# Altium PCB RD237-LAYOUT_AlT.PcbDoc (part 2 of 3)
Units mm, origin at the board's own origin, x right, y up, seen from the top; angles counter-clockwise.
Board outline 100 x 82 mm, 4 copper layers (Top Layer, GND2, POWER 3, Bottom Layer), stack 1.444 mm thick; 308 components, 134 nets, 738 pads, 304 vias.
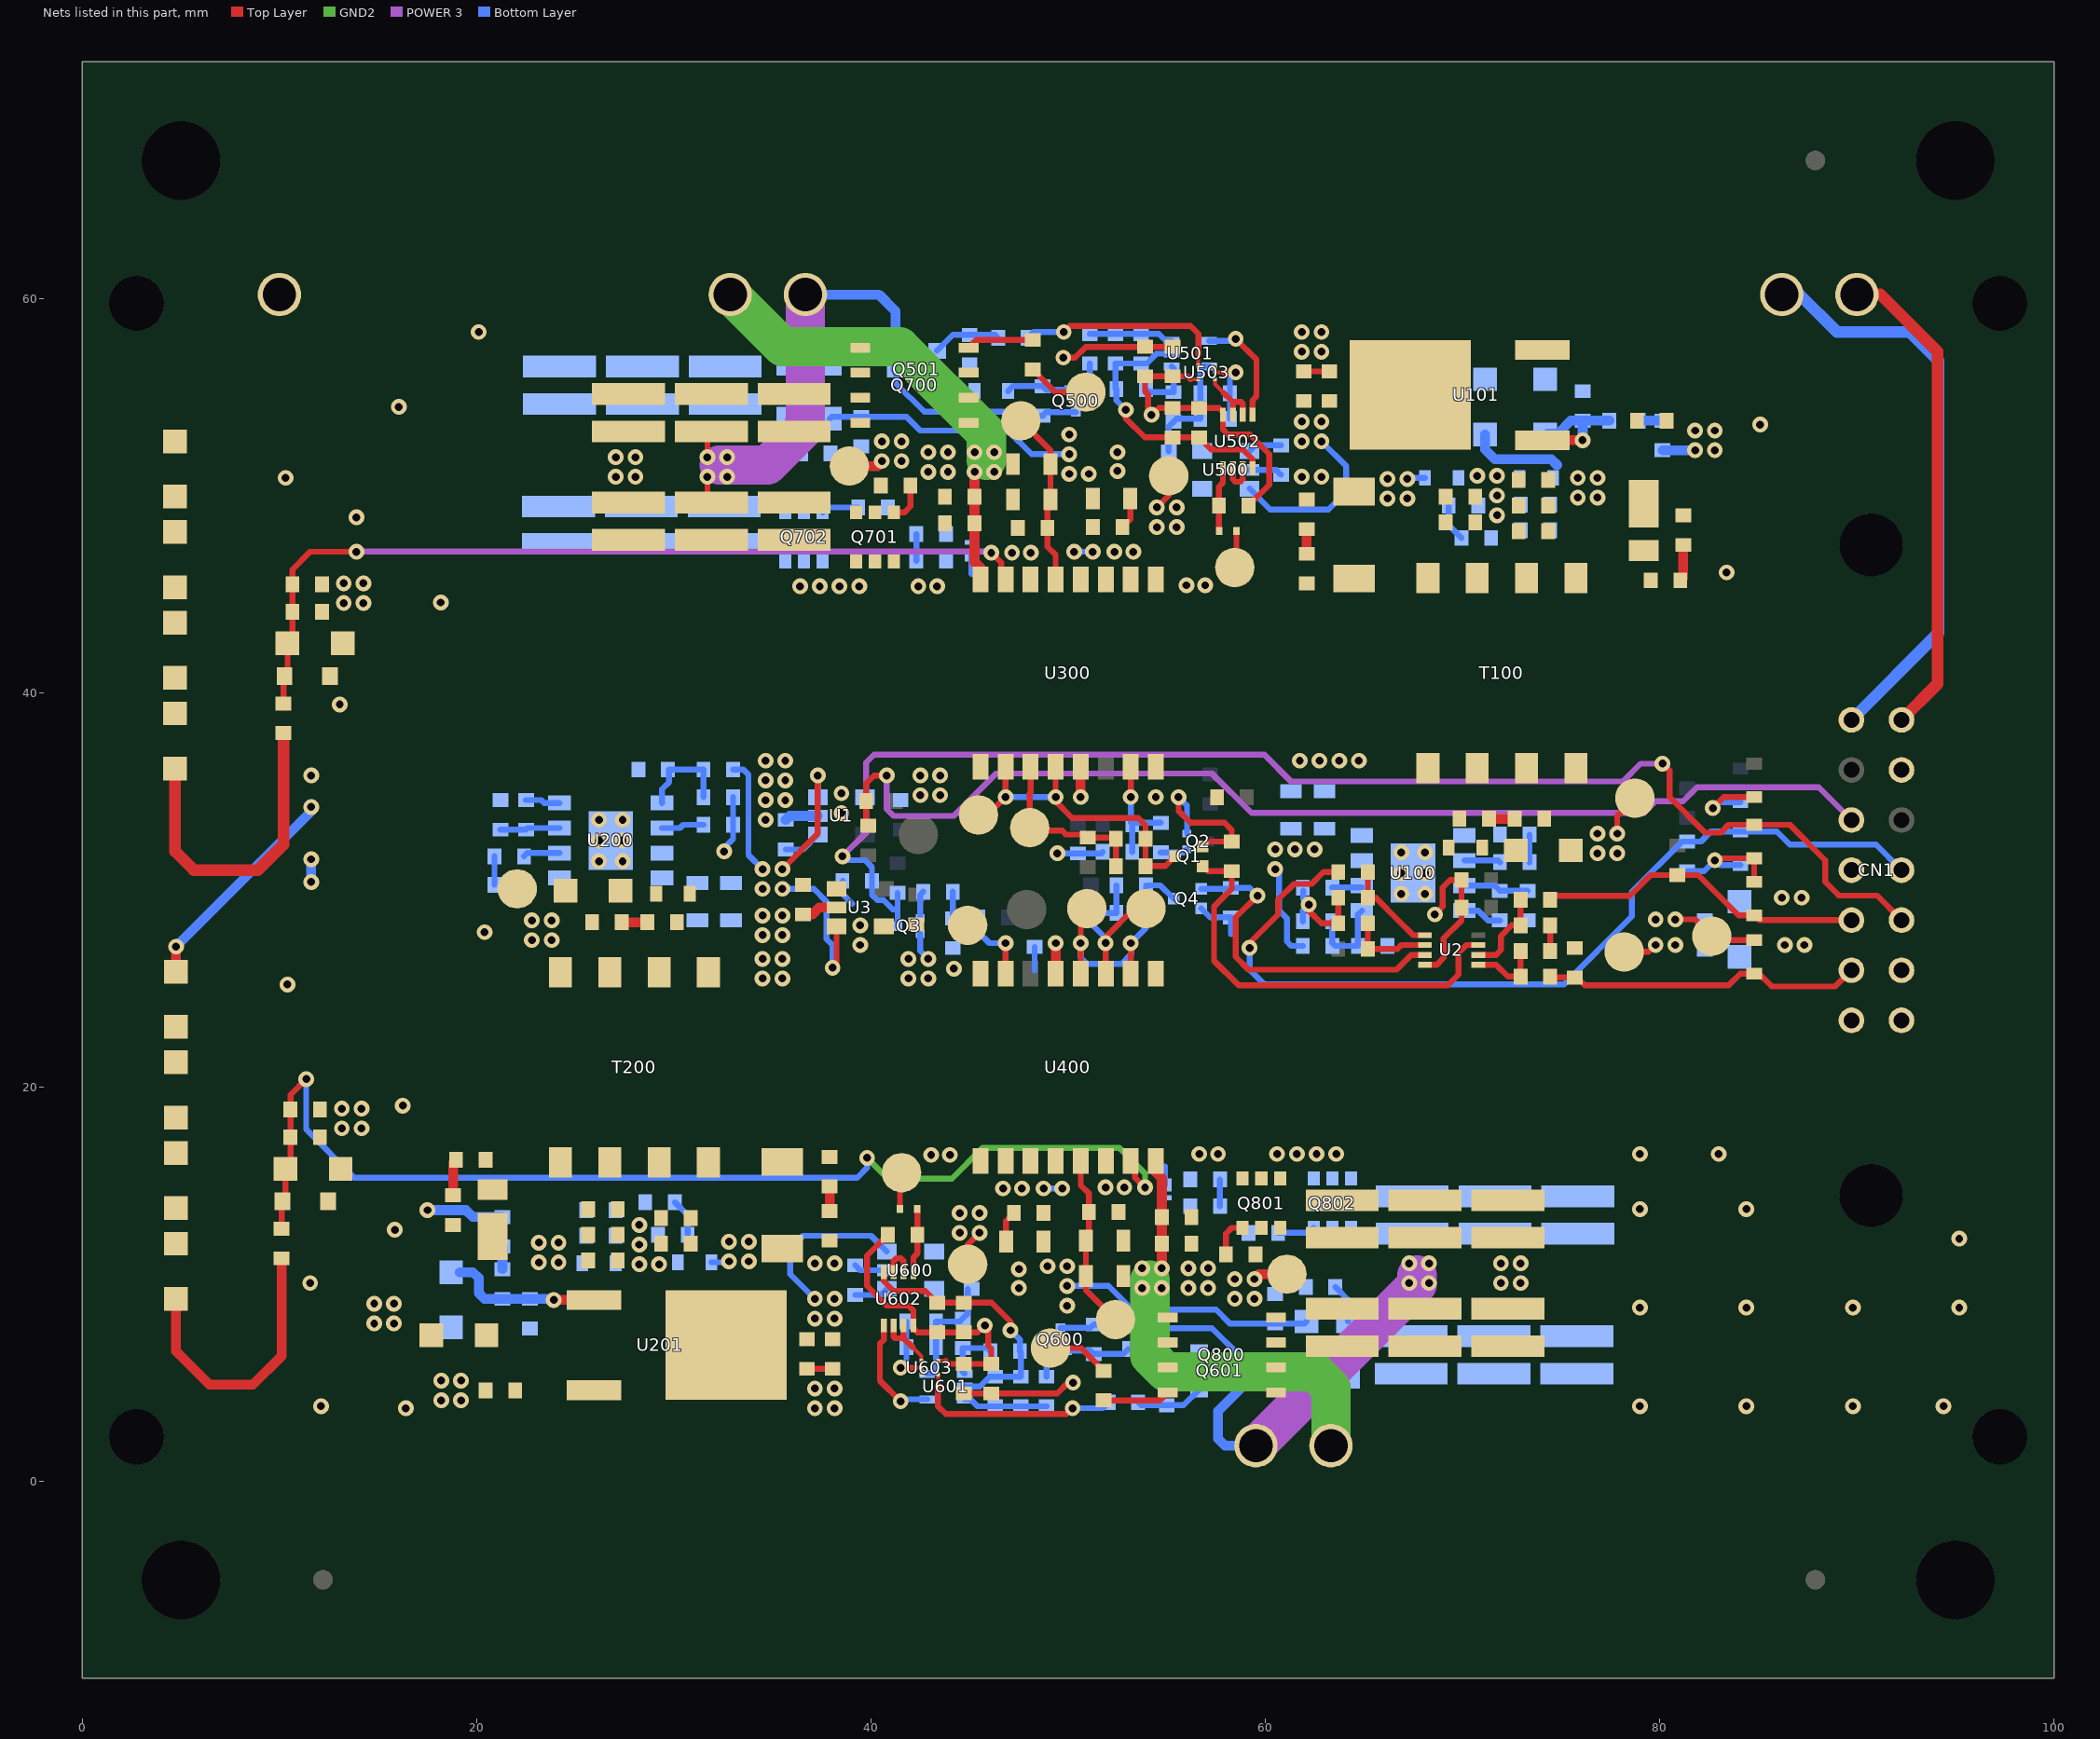
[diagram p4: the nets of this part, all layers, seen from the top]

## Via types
v1: diameter 0.8, hole 0.4, Top Layer to Bottom Layer, 304 vias

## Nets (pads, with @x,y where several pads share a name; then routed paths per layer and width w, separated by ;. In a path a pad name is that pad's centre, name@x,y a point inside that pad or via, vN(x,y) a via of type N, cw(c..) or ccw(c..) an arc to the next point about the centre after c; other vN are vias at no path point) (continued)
A_INA: CN1.7 D2.1 R9.2 R13.2 | length 45.9
  Top Layer w0.3: v1(59.2,27.05) 59.2,27.3 60.65,28.75 60.65,29.5 61.45,30.3 62.35,30.3 62.95,30.9 R9.2@63.7,30.9
  Bottom Layer w0.3: v1(59.2,27.05) 59.2,25.95 59.95,25.2 75.15,25.2 78.6,28.65 78.6,29.9 81.15,32.45 R13.2@81.4,32.45 82.1,32.45 82.6,32.95 D2.1@84.1,32.95 85.95,32.95 86.61,32.29 90.98,32.29 CN1.7@92.27,31
A_INB(NC): CN1.10 R20.2 R21.2 | length 57.1
  Top Layer w0.3: R21.2@39.85,33.25 39.75,33.35 R20.2@39.75,34.5 39.75,35.4 40.15,35.8 v1(40.8,35.8)
  POWER 3 w0.3: v1(40.8,35.8) 40.8,34.1 41.15,33.75 44.2,33.75 46.35,35.9 57.3,35.9 59.3,33.9 79.2,33.9 79.8,34.5 81.2,34.5 81.9,35.2 88.07,35.2 CN1.10@89.73,33.54
B_ENA: CN1.6 D3.1 R4.2 R6.2 | length 16.7
  Top Layer w0.3: R6.2@74.45,29.5 74.65,29.7 78.5,29.7 79.55,30.75 R4.2@80.9,30.75 81.95,30.75 84,28.7 D3.1@84.8,28.7 85.04,28.46 CN1.6@89.73,28.46
B_FLT: C19.2 CN1.5 D6.1 Q3.3 R16.1 | length 70.3
  Top Layer w0.3: v1(80.15,36.4) 80.5,36.05 80.5,34.7 82.3,32.9 83.1,32.9 83.5,33.3 D6.1@84.8,33.3 86.6,33.3 88.4,31.5 88.4,30.4 89.09,29.71 91.02,29.71 CN1.5@92.27,28.46
  POWER 3 w0.3: v1(38.55,31.7) 39.75,32.9 39.75,36.45 40.15,36.85 59.95,36.85 61.3,35.5 78.15,35.5 79.05,36.4 v1(80.15,36.4)
  Bottom Layer w0.3: v1(38.55,31.7) 38.75,31.5 39.7,31.5 40.05,31.15 C19.2@40.05,30.45 40.05,29.75 40.325,29.475 40.625,29.475 41.093,29.006 41.344,29.006 ; Q3.3@41.35,28.15 41.35,29 R16.1@41.35,29.85
B_INA: CN1.4 D5.1 R7.2 R14.2 | length 16.3
  Top Layer w0.3: R7.2@74.45,25.6 74.5,25.55 R14.2@75.7,25.55 75.8,25.55 76.2,25.15 83.5,25.15 84.1,25.75 D5.1@84.8,25.75 85.032,25.75 85.682,25.1 88.91,25.1 CN1.4@89.73,25.92
B_INB(NC): CN1.3
B_RDY(NC): CN1.8
GND: C1.1 C2.1 C3.1 C4.1 C6.1 C7.1 C8.1 C9.1 C10.1 C11.1 C12.1 C13.1 C15.1 C16.1 C17.1 C18.1 C19.1 C100.1 C101.1 C102.1 C114.1 C200.1 C201.1 C202.1 C214.1 CN1.1 CN1.11 D1.1 D2.2 D3.2 D4.2 D5.2 D6.2 D7.2 Q1.2 Q2.2 Q3.2 Q4.2 R11.1 R13.1 R14.1 R22.1 R101.1 R106.1 R201.1 R206.1 TP3.1 TP17.1 U1.2 U2.4 U3.2 U100.4 U100.9 U200.4 U200.9 U300.5 U300.8 U400.5 U400.8 | length 55.5
  Top Layer w0.3: v1(55.6,34.7) 55.6,34 56.2,33.4 57.925,33.4 58.3,33.025 R11.1@58.3,32.45 57.075,32.45 Q1.2@56.825,32.2 ; v1(62.2,29.25) 62.2,28.95 62.85,28.3 C9.1@63.7,28.3 C10.1@63.7,29.6 ; U2.4@68.1,26.2 68.7,26.2 69.05,26.55 69.05,27.55 69.95,28.45 C8.1@69.95,29.1 C7.1@69.95,30.5 69.375,30.5 69,30.125 69,29.15 v1(68.6,28.75) ; C11.1@74.45,26.9 C12.1@74.45,28.2 ; v1(80.8,28.5) 81.8,28.5 TP3.1@82.65,27.65 82.85,27.45 D5.2@84.8,27.45 ; v1(82.7,34.15) 83.25,34.7 D7.2@84.8,34.7 ; v1(82.8,31.5) 82.9,31.6 D6.2@84.8,31.6 D3.2@84.8,30.4
  Top Layer w0.5: C16.1@36.55,28.75 37.021,28.75 37.371,29.1 U3.2@38.25,29.1 ; U400.5@49.365,25.75 v1(49.365,27.295) ; v1(50.635,34.705) U300.5@50.635,36.25
  Bottom Layer w0.3: v1(32.55,31.95) 32.55,32.127 33,32.577 C200.1@33,33.3 C214.1@33,34.7 ; C19.1@38.575,30.45 38.575,29.775 39.05,29.3 ; Q3.2@42.5,27.75 42.5,26.9 v1(42.9,26.5) ; 48.3,25.9 C13.1@48.3,27.1 ; v1(49.45,31.85) C4.1@50.5,31.85 51.675,31.85 C6.1@51.75,31.925 ; v1(55.6,34.7) 56.025,34.275 Q2.2@56.025,32.85 ; Q4.2@56.75,29.05 57.2,28.6 R22.1@58.25,28.6 58.25,27.75 ; C114.1@61.9,28.4 61.9,28.95 v1(62.2,29.25) 61.934,29.516 C100.1@61.934,29.961 ; R13.1@81.4,30.95 82.25,30.95 v1(82.8,31.5) 83.05,31.25 D2.2@84.1,31.25 ; v1(82.7,34.15) 83,34.45 D4.2@84.1,34.45
  Bottom Layer w0.5: C2.1@35.675,33.55 35.875,33.75 U1.2@37.3,33.75
  other v1: 34.5,25.5 35.5,25.5 41.9,25.5 42.9,25.5 44.2,26 34.5,26.5 35.5,26.5 41.9,26.5 39.45,27.2 34.5,27.7 35.5,27.7 20.4,27.85 39.45,28.2 79.8,28.5 34.5,28.7 35.5,28.7 86.2,29.6 87.2,29.6 66.9,29.8 68.1,29.8 66.9,30.85 68.1,30.85 26.2,31.45 27.4,31.45 66.9,31.9 68.1,31.9 26.2,32.5 27.4,32.5 26.2,33.55 27.4,33.55 34.65,33.55 38.5,33.895 34.65,34.55 35.65,34.55 54.445,34.705 42.5,34.8 43.5,34.8 38.5,34.895 34.65,35.55 35.65,35.55 42.5,35.8 43.5,35.8 34.65,36.55 35.65,36.55 61.75,36.55 62.75,36.55 63.75,36.55 64.75,36.55
NC_1A: U500.4
NC_1B: U600.4
NC_2A: U503.3
NC_2B: U603.3
NC_A: U1.4
NC_B: U3.4
NetC5_1: C5.1 Q1.3 R5.1 TP7.1 U300.2 U300.4 | length 16.4
  Top Layer w0.3: TP7.1@45.45,33.8 45.92,33.8 v1(46.825,34.705) U300.2@46.825,36.25 ; U300.4@49.365,36.25 v1(49.365,34.705) 49.365,34.485 50.2,33.65 53.55,33.65 53.925,33.275 C5.1@53.925,32.6 R5.1@53.925,31.2 54.925,31.2 Q1.3@55.425,31.7
  Bottom Layer w0.3: v1(46.825,34.705) v1(49.365,34.705)
NetC5_2: C5.2 R1.1 R5.2 TP8.1 U300.3 | length 9.1
  Top Layer w0.3: U300.3@48.095,36.25 48.095,34.95 48.05,34.905 TP8.1@48.05,33.15 48.2,33 49.7,33 49.9,32.8 50.85,32.8 R1.1@51,32.65 52.375,32.65 C5.2@52.425,32.6 R5.2@52.425,31.2
NetC6_2: C6.2 R3.1 R8.2 U300.7 | length 5.8
  Top Layer w0.3: v1(53.175,34.705) U300.7@53.175,36.25
  Bottom Layer w0.3: v1(53.175,34.705) 53.175,33.4 R3.1@53.25,33.325 ; C6.2@53.25,31.925 R3.1@53.25,33.325 ; R8.2@54.7,33.4 53.325,33.4 R3.1@53.25,33.325
NetC9_2: C9.2 R10.1 U2.2 | length 4.2
  Top Layer w0.3: C9.2@65.2,28.3 R10.1@65.2,27 66.65,27 ; 66.7,27 66.9,27.2 U2.2@68.1,27.2
NetC10_2: C10.2 R9.1 U2.1 | length 5
  Top Layer w0.3: R9.1@65.2,30.9 C10.2@65.2,29.6 65.6,29.6 66.75,28.45 67.5,27.7 U2.1@68.1,27.7
NetC11_2: C11.2 R7.1 U2.5 | length 3.7
  Top Layer w0.3: U2.5@70.8,26.2 71.7,26.2 72.3,25.6 R7.1@72.95,25.6 C11.2@72.95,26.9
NetC12_2: C12.2 R6.1 U2.6 | length 4.7
  Top Layer w0.3: U2.6@70.8,26.7 71.7,26.7 71.95,26.95 71.95,27.65 72.5,28.2 C12.2@72.95,28.2 R6.1@72.95,29.7
NetC14_1: C14.1 Q4.3 R18.1 TP19.1 U400.2 U400.4 | length 14.1
  Top Layer w0.3: U400.4@50.635,25.75 v1(50.635,27.295) 50.635,28.735 TP19.1@50.95,29.05 ; U400.2@53.175,25.75 v1(53.175,27.295)
  Bottom Layer w0.3: v1(50.635,27.295) 50.635,26.565 50.95,26.25 52.7,26.25 53.175,26.725 v1(53.175,27.295) 53.95,28.07 R18.1@53.95,28.825 C14.1@53.95,30.225 54.675,30.225 Q4.3@55.35,29.55
NetC14_2: C14.2 R15.1 R18.2 TP18.1 U400.3 | length 9
  Top Layer w0.3: U400.3@51.9,25.755 v1(51.9,27.3) 51.9,27.6 53.35,29.05 TP18.1@53.95,29.05
  Bottom Layer w0.3: v1(51.9,27.3) 51.9,27.55 51.15,28.3 R15.1@51.15,28.775 51.2,28.825 R18.2@52.45,28.825 C14.2@52.45,30.225
NetC15_2: C15.2 R17.1 R19.2 U400.7 | length 6.6
  Top Layer w0.3: U400.7@46.825,25.75 v1(46.825,27.295)
  Bottom Layer w0.3: R19.2@44.15,29.9 C15.2@44.15,28.55 44.2,28.6 R17.1@45.45,28.6 45.45,27.85 46.005,27.295 v1(46.825,27.295)
NetC100_2: C100.2 U100.2 | length 1.5
  Bottom Layer w0.3: C100.2@63.4,30.115 U100.2@64.898,30.115
NetC103_1: C103.1 D101.1 R105.1 T100.1 T100.2 TP100.1 U100.5 | length 2.2
  Top Layer w0.3: v1(77.85,32.85) 77.85,33.75 TP100.1@78.75,34.65
  other v1: 76.85,31.85 77.85,31.85 76.85,32.85
NetC103_2: C103.2 R102.1 | length 1.3
  Top Layer w0.5: R102.1@71.35,33.6 C103.2@72.65,33.6
NetC104_1: C104.1 C106.2 C108.2 C110.2 C111.2 D102.1 D104.1 D106.2 R110.2 R112.2 U101.3 | length 4.7
  Bottom Layer w0.5: D106.2@71.15,53.1 71.15,52.345 71.645,51.85 74.5,51.85 74.8,51.55
  other v1: 75.85,49.9 76.85,49.9 75.85,50.9 76.85,50.9
NetC104_2: C104.2 R107.1 | length 1.9
  Top Layer w0.5: R107.1@81.05,45.7 81.2,45.85 C104.2@81.2,47.5
NetC105_2: C105.2 R108.1 | length 1.3
  Top Layer w0.5: R108.1@62.1,47.05 C105.2@62.1,48.3
NetC114_2: C114.2 R100.1 R101.2 U100.1 | length 4.3
  Bottom Layer w0.3: C114.2@63.4,28.4 63.4,27.3 63.55,27.15 R101.2@64.7,27.15 64.7,28.747 U100.1@64.898,28.945
NetC200_2: C200.2 U200.2 | length 2.2
  Bottom Layer w0.3: U200.2@29.401,33.135 30.31,33.135 30.475,33.3 C200.2@31.5,33.3
NetC203_1: C203.1 D201.1 R205.1 T200.1 T200.2 TP200.1 U200.5
  other v1: 22.8,27.45 23.8,27.45 22.8,28.45 23.8,28.45
NetC203_2: C203.2 R202.1 | length 1.3
  Top Layer w0.5: C203.2@27.35,28.35 R202.1@28.65,28.35
NetC204_1: C204.1 C206.2 C208.2 C210.2 C211.2 D202.1 D204.1 D206.2 R210.2 R212.2 U201.3
  other v1: 23.15,11.1 24.15,11.1 23.15,12.1 24.15,12.1
NetC204_2: C204.2 R207.1 | length 1.9
  Top Layer w0.5: C204.2@18.8,14.5 18.8,16.15 R207.1@18.95,16.3
NetC205_2: C205.2 R208.1 | length 1.3
  Top Layer w0.5: C205.2@37.9,13.7 R208.1@37.9,14.95
NetC214_2: C214.2 R200.1 R201.2 U200.1 | length 5
  Bottom Layer w0.3: U200.1@29.401,34.405 29.401,35.101 29.75,35.45 29.75,36.1 R200.1@31.5,36.1 C214.2@31.5,34.7
NetC501_2: C501.2 C503.2 C504.2 C505.2 C506.2 C507.2 C508.2 R500.2 R505.2 U500.5 U501.5 U502.8 U503.5 | length 21.5
  Top Layer w0.2: 56.2,55.9 U503.5@56.6,55.9
  Top Layer w0.3: v1(54.225,54.1) 54.05,54.275 54.05,55.138 53.9,55.288 C507.2@53.9,56.05 C508.2@55.3,56.05 56.05,56.05 56.2,55.9 ; v1@54.25,54.1 54.6,54.45 C505.2@55.3,54.45 C506.2@56.65,54.45 57.65,54.45 57.85,54.25 U502.8@57.85,54.1 57.85,53.35 58.1,53.1 59.2,53.1 60.2,52.1 60.2,50.55 R505.2@59.15,49.5
  Bottom Layer w0.3: C501.2@55.1,52.25 55.1,53.5 R500.2@55.35,53.75 55.5,53.9 C503.2@56.7,53.9 C504.2@56.7,55.2 56.7,56.4 56.85,56.55 U501.5@57.15,56.55
NetC502_2: C502.2 R503.1 R504.2 U501.3 | length 4.3
  Bottom Layer w0.3: R503.1@51.1,58.2 C502.2@52.4,58.2 R504.2@53.7,58.2 54.6,58.2 54.95,57.85 U501.3@55.25,57.85
NetC601_2: C601.2 C603.2 C604.2 C605.2 C606.2 C607.2 C608.2 R600.2 R605.2 U600.5 U601.5 U602.8 U603.5 | length 21.5
  Top Layer w0.2: U603.5@43.4,6.1 43.8,6.1
  Top Layer w0.3: R605.2@40.85,12.5 39.8,11.45 39.8,9.9 40.8,8.9 41.9,8.9 42.15,8.65 U602.8@42.15,7.9 42.15,7.75 42.35,7.55 C606.2@43.35,7.55 C605.2@44.7,7.55 45.4,7.55 v1@45.75,7.9 ; 43.8,6.1 43.95,5.95 C608.2@44.7,5.95 C607.2@46.1,5.95 46.1,6.712 45.95,6.862 45.95,7.725 v1(45.775,7.9)
  Bottom Layer w0.3: U601.5@42.85,5.45 43.15,5.45 43.3,5.6 C604.2@43.3,6.8 C603.2@43.3,8.1 44.5,8.1 R600.2@44.65,8.25 44.9,8.5 C601.2@44.9,9.75
NetC602_2: C602.2 R603.1 R604.2 U601.3 | length 4.3
  Bottom Layer w0.3: U601.3@44.75,4.15 45.05,4.15 45.4,3.8 R604.2@46.3,3.8 C602.2@47.6,3.8 R603.1@48.9,3.8
NetC700_2: C700.2 D701.2 D702.2 R702.1 R708.2 U300.15 | length 44.5
  Top Layer w0.3: R708.2@10.2,39.45 10.2,40.8 D702.2@10.25,40.85 10.4,41 D701.2@10.4,42.5 10.65,42.75 C700.2@10.65,44.1 R702.1@10.65,45.5 10.65,46.25 11.55,47.15 v1(13.9,47.15) ; v1(46.1,47.1) 46.35,46.85 46.6,46.6 46.6,45.975 U300.15@46.825,45.75
  POWER 3 w0.3: v1@13.913,47.163 46.037,47.163 v1(46.1,47.1)
NetC800_2: C800.2 D801.2 D802.2 R802.1 R808.2 U400.15 | length 58.9
  Top Layer w0.3: R808.2@10.1,12.8 10.1,14.15 D802.2@10.15,14.2 10.3,14.35 D801.2@10.3,15.85 ; D801.2@10.304,15.845 10.55,16.091 C800.2@10.55,17.45 ; C800.2@10.556,17.45 10.556,18.844 R802.1@10.55,18.85 10.55,19.6 v1(11.35,20.4) ; U400.15@53.175,16.25 53.4,16.025 53.4,15.4 v1(53.9,14.9)
  GND2 w0.3: v1(39.8,16.4) 40.85,15.35 44.1,15.35 45.65,16.9 52.6,16.9 53.9,15.6 v1(53.9,14.9)
  Bottom Layer w0.3: v1(11.35,20.4) 11.35,17.85 13.8,15.4 39.3,15.4 39.8,15.9 v1(39.8,16.4)
NetD100_1: D100.1 D101.2
NetD102_2: D102.2 R107.2 T100.8
NetD103_2: D103.2 R108.2 T100.5
NetD107_1: D107.1 R113.2 R115.1 U101.1 | length 6.6
  Top Layer w0.5: U101.1@74.05,52.81 v1(76.09,52.81)
  Bottom Layer w0.5: D107.1@74.2,53 74.35,53.15 74.85,53.15 75.5,53.8 R115.1@76.1,53.8 ; v1(76.09,52.81) 76.1,52.82 R115.1@76.1,53.8 ; R113.2@77.45,53.8 R115.1@76.1,53.8
NetD200_1: D200.1 D201.2
NetD202_2: D202.2 R207.2 T200.8
NetD203_2: D203.2 R208.2 T200.5
NetD207_1: D207.1 R213.2 R215.1 U201.1 | length 7.8
  Top Layer w0.5: v1(23.91,9.19) U201.1@25.95,9.19
  Bottom Layer w0.5: D207.1@19.15,10.6 19.807,10.6 20.1,10.307 20.1,9.543 20.393,9.25 ; 20.393,9.25 R215.1@22.7,9.25 23.85,9.25 v1(23.91,9.19)
NetD500_1: D500.1 Q500.1 R502.1 | length 3.2
  Bottom Layer w0.3: D500.1@46.95,55.3 47.2,55.55 R502.1@48.7,55.55 48.875,55.375 Q500.1@50,55.375
NetD501_1: D501.1 D700.1 R701.2 TP11.1 U300.11 | length 2.8
  Top Layer w0.3: TP11.1@58.45,46.35 58.538,46.437 D501.1@58.538,48.2
  Bottom Layer w0.3: 45.1,46.03 D700.1@45.1,46.975
  other v1: 56,45.45 56.95,45.45 52.35,47.15 53.3,47.15
NetD501_2: D501.2 R505.1 U502.1 | length 3.3
  Top Layer w0.3: D501.2@57.65,48.212 R505.1@57.65,49.5 57.65,50.45 57.85,50.65 U502.1@57.85,51.4
NetD600_1: D600.1 Q600.1 R602.1 | length 3.2
  Bottom Layer w0.3: Q600.1@50,6.625 51.125,6.625 R602.1@51.3,6.45 52.8,6.45 D600.1@53.05,6.7
NetD601_1: D601.1 D800.1 R801.2 TP21.1 U400.11 | length 2.8
  Top Layer w0.3: D601.1@41.462,13.8 41.462,15.563 TP21.1@41.55,15.65
  Bottom Layer w0.3: D800.1@54.9,15.025 54.9,15.97
  other v1: 46.7,14.85 47.65,14.85 43.05,16.55 44,16.55
NetD601_2: D601.2 R605.1 U602.1 | length 3.3
  Top Layer w0.3: U602.1@42.15,10.6 42.15,11.35 42.35,11.55 R605.1@42.35,12.5 D601.2@42.35,13.788
NetD700_2: D700.2 R703.2
NetD703_1: D703.1 R708.1 | length 16.3
  Top Layer w0.6: D703.1@4.7,36.15 4.7,31.95 5.65,31 8.9,31 10.2,32.3 R708.1@10.2,37.95
NetD703_2: D703.2 D704.1
NetD704_2: D704.2 D705.1
NetD705_2: D705.2 D706.1
NetD706_2: D706.2 P7.1
NetD707_1: D707.1 D708.2 P4.1 Q500.3 Q501.3 R502.2 R704.2 R705.2 R706.2 R707.2 R709.2 R710.2 R721.1 R722.1 R723.1 | length 33.1
  Top Layer w0.3: v1(31.7,50.95) 31.7,49.85 R707.2@31.9,49.65 ; v1(31.7,51.95) 31.7,53.05 R705.2@31.9,53.25
  POWER 3 w2: 32.3,51.55 34.75,51.55 36.67,53.47 P4.1@36.67,60.2
  Bottom Layer w0.3: Q501.3@41.25,56.4 41.25,55.7 42.7,54.25 47.5,54.25 47.7,54.05 R502.2@48.7,54.05 48.875,54.225 Q500.3@50.4,54.225
  Bottom Layer w0.5: P4.1@36.67,60.2 40.4,60.2 41.25,59.35 Q501.3@41.25,56.4
  other v1: 27.05,50.95 28.05,50.95 32.7,50.95 27.05,51.95 28.05,51.95 32.7,51.95
NetD800_2: D800.2 R803.2
NetD803_1: D803.1 R808.1 | length 14.3
  Top Layer w0.5: D803.1@4.75,9.25 4.75,6.6 6.45,4.9 8.65,4.9 10.1,6.35 R808.1@10.1,11.3
NetD803_2: D803.2 D804.1
NetD804_2: D804.2 D805.1
NetD805_2: D805.2 D806.1
NetD807_1: D807.1 D808.2 P11.1 Q600.3 Q601.3 R602.2 R804.2 R805.2 R806.2 R807.2 R809.2 R810.2 R821.1 R822.1 R823.1 | length 28.6
  POWER 3 w2: P11.1@59.52,1.8 67.7,9.98 67.7,10.45
  Bottom Layer w0.3: Q600.3@49.6,7.775 51.125,7.775 R602.2@51.3,7.95 52.15,7.95 52.35,7.75 57.3,7.75 58.75,6.3 Q601.3@58.75,5.6
  Bottom Layer w0.5: Q601.3@58.75,5.6 58.75,4.7 57.6,3.55 57.6,2.15 57.95,1.8 P11.1@59.52,1.8
  other v1: 67.3,10.05 68.3,10.05 71.95,10.05 72.95,10.05 67.3,11.05 68.3,11.05 71.95,11.05 72.95,11.05
NetQ1_1: Q1.1 R11.2 U2.7 | length 21.9
  Top Layer w0.3: Q1.1@56.825,31.2 57.075,30.95 R11.2@58.3,30.95 58.3,30.05 57.4,29.15 57.4,26.4 58.65,25.15 69.25,25.15 69.8,25.7 69.8,26.8 70.2,27.2 U2.7@70.8,27.2
NetQ2_1: Q2.1 R8.1 | length 1.4
  Bottom Layer w0.3: R8.1@54.7,31.9 55.875,31.9 Q2.1@56.025,32.05
NetQ3_1: Q3.1 R19.1 | length 1.4
  Bottom Layer w0.3: Q3.1@42.5,28.55 42.5,29.75 R19.1@42.65,29.9
NetQ4_1: Q4.1 R22.2 U2.3 | length 16.8
  Top Layer w0.3: v1(59.6,29.7) 58.5,28.6 58.5,26.6 59.15,25.95 66.65,25.95 67.4,26.7 U2.3@68.1,26.7
  Bottom Layer w0.3: Q4.1@56.75,30.05 58.2,30.05 R22.2@58.25,30.1 59.2,30.1 v1(59.6,29.7)
NetQ500_2: Q500.2 R503.2 | length 1.4
  Bottom Layer w0.3: Q500.2@50.8,55.375 51.1,55.675 R503.2@51.1,56.7
NetQ501_1: Q501.1 R506.1 R507.2 | length 3.5
  Bottom Layer w0.3: Q501.1@43.35,57.35 44.15,58.15 R507.2@45,58.15 46.3,58.15 R506.1@46.45,58
NetQ600_2: Q600.2 R603.2 | length 1.4
  Bottom Layer w0.3: R603.2@48.9,5.3 48.9,6.325 Q600.2@49.2,6.625
NetQ601_1: Q601.1 R606.1 R607.2 | length 3.5
  Bottom Layer w0.3: R606.1@53.55,4 53.7,3.85 R607.2@55,3.85 55.85,3.85 Q601.1@56.65,4.65
NetQ700_4: Q700.4 R700.1 | length 3.4
  Top Layer w0.3: Q700.4@44.95,57.505 45.345,57.9 R700.1@48.2,57.9
NetQ700_5: Q700.5 Q700.6 Q700.7 Q700.8 R704.1 R705.1 R709.1
NetQ701_1: Q701.1 Q701.2 Q701.5 Q701.6 R706.1 R707.1 R710.1
NetQ701_3: Q701.3 R701.1 R703.1 | length 1.3
  Bottom Layer w0.3: R701.1@42.3,46.7 R703.1@42.3,48.05
  other v1: 42.4,45.4 43.35,45.4
NetQ702_1: Q702.1 Q702.2 Q702.5 Q702.6 R718.2 R719.2 R720.2
NetQ702_3: Q702.3 R713.1 | length 1.9
  Bottom Layer w0.3: Q702.3@37.55,49.15 37.8,49.4 R713.1@39.35,49.4
NetQ800_4: Q800.4 R800.1 | length 3.4
  Top Layer w0.3: R800.1@51.8,4.1 54.655,4.1 Q800.4@55.05,4.495
NetQ800_5: Q800.5 Q800.6 Q800.7 Q800.8 R804.1 R805.1 R809.1
NetQ801_1: Q801.1 Q801.2 Q801.5 Q801.6 R806.1 R807.1 R810.1
NetQ801_3: Q801.3 R801.1 R803.1 | length 1.3
  Bottom Layer w0.3: R803.1@57.7,13.95 R801.1@57.7,15.3
  other v1: 56.65,16.6 57.6,16.6
NetQ802_1: Q802.1 Q802.2 Q802.5 Q802.6 R818.2 R819.2 R820.2
NetQ802_3: Q802.3 R813.1 | length 1.9
  Bottom Layer w0.3: R813.1@60.65,12.6 62.2,12.6 Q802.3@62.45,12.85
NetR103_1: R103.1 R106.2 U100.7 | length 3.3
  Bottom Layer w0.3: U100.7@70.101,30.215 71.635,30.215 R103.1@71.9,29.95 R106.2@73.3,29.95
NetR103_2: R103.2 U100.8 | length 2
  Bottom Layer w0.3: U100.8@70.101,28.945 70.805,28.945 71.3,28.45 R103.2@71.9,28.45
NetR104_1: R104.1 R105.2 | length 1.4
  Bottom Layer w0.3: R104.1@73.4,31.4 R105.2@73.4,32.8
NetR104_2: R104.2 U100.6 | length 1.8
  Bottom Layer w0.3: U100.6@70.101,31.485 71.815,31.485 R104.2@71.9,31.4
NetR113_1: R113.1 R114.2 | length 1.2
  Bottom Layer w0.5: R113.1@78.95,53.8 R114.2@80.15,53.8
NetR203_1: R203.1 R206.2 U200.7 | length 3
  Bottom Layer w0.3: R206.2@21.2,33.05 R203.1@22.48,33.05 ; R203.1@22.5,33.05 22.585,33.135 U200.7@24.198,33.135
NetR203_2: R203.2 U200.8 | length 1.8
  Bottom Layer w0.3: R203.2@22.5,34.55 23.277,34.55 23.422,34.405 U200.8@24.198,34.405
NetR204_1: R204.1 R205.2 | length 1.5
  Bottom Layer w0.3: R205.2@20.9,30.25 R204.1@20.9,31.7
NetR204_2: R204.2 U200.6 | length 1.9
  Bottom Layer w0.3: R204.2@22.4,31.7 22.565,31.865 U200.6@24.198,31.865
NetR213_1: R213.1 R214.2 | length 1.2
  Bottom Layer w0.5: R213.1@21.3,10.75 R214.2@21.3,11.9
NetR500_1: R500.1 R501.2 U501.1 | length 2.8
  Bottom Layer w0.3: R501.2@53.95,55.4 54.1,55.25 R500.1@55.35,55.25 55.35,56.45 U501.1@55.25,56.55
NetR506_2: R506.2 U503.4 | length 10.7
  Top Layer w0.2: U503.4@56.6,56.6 56.6,57.129
  Top Layer w0.3: v1(49.775,58.3) 50.075,58.6 56.2,58.6 56.6,58.2 56.6,57.129
  Bottom Layer w0.3: R506.2@47.95,58 48.25,58.3 v1(49.775,58.3)
NetR600_1: R600.1 R601.2 U601.1 | length 2.8
  Bottom Layer w0.3: U601.1@44.75,5.45 44.65,5.55 R600.1@44.65,6.75 45.9,6.75 R601.2@46.05,6.6
NetR606_2: R606.2 U603.4 | length 10.7
  Top Layer w0.2: 43.4,4.871 U603.4@43.4,5.4
  Top Layer w0.3: 43.4,4.871 43.4,3.8 43.8,3.4 49.925,3.4 v1(50.225,3.7)
  Bottom Layer w0.3: v1(50.225,3.7) 51.75,3.7 R606.2@52.05,4
NetR700_2: R700.2 TP10.1 U300.12 | length 4.1
  Top Layer w0.3: R700.2@48.2,56.4 49.35,55.25 TP10.1@50.9,55.25
  Bottom Layer w0.3: v1(50.3,47.15) v1(51.25,47.15)
  other v1: 52.5,51.25 52.5,52.2
NetR713_2: R713.2 U300.14
  other v1: 47.15,47.1 48.1,47.1
NetR718_1: R718.1 R719.1 R720.1 R721.2 R722.2 R723.2
NetR800_2: R800.2 TP20.1 U400.12 | length 4.1
  Top Layer w0.3: TP20.1@49.1,6.75 50.65,6.75 R800.2@51.8,5.6
  Bottom Layer w0.3: v1(48.75,14.85) v1(49.7,14.85)
  other v1: 47.5,9.8 47.5,10.75
NetR813_2: R813.2 U400.14
  other v1: 51.9,14.9 52.85,14.9
NetR818_1: R818.1 R819.1 R820.1 R821.2 R822.2 R823.2
NetU501_4: U501.4 U502.5 | length 5.8
  Top Layer w0.3: v1(58.5,57.95) 59.55,56.9 59.55,55.029 59.35,54.829 U502.5@59.35,54.1
  Bottom Layer w0.3: U501.4@57.15,57.85 58.4,57.85 v1(58.5,57.95)
NetU502_2: U502.2 U502.3 | length 1.8
  Top Layer w0.3: U502.2@58.35,51.4 58.35,50.821 58.475,50.696 58.725,50.696 58.85,50.821 U502.3@58.85,51.4
NetU502_6: U502.6 U502.7 U503.1 | length 3.3
  Top Layer w0.2: U503.1@57.45,55.9 57.45,55.65 57.875,55.225
  Top Layer w0.3: 57.875,55.225 58.35,54.75 ; U502.7@58.35,54.1 58.35,54.75 ; U502.6@58.85,54.1 58.85,54.679 58.779,54.75 58.35,54.75
NetU601_4: U601.4 U602.5 | length 5.8
  Top Layer w0.3: U602.5@40.65,7.9 40.65,7.171 40.45,6.971 40.45,5.1 v1(41.5,4.05)
  Bottom Layer w0.3: v1(41.5,4.05) 41.6,4.15 U601.4@42.85,4.15
NetU602_2: U602.2 U602.3 | length 1.8
  Top Layer w0.3: U602.3@41.15,10.6 41.15,11.179 41.275,11.304 41.525,11.304 41.65,11.179 U602.2@41.65,10.6
NetU602_6: U602.6 U602.7 U603.1 | length 3.3
  Top Layer w0.2: 42.125,6.775 42.55,6.35 U603.1@42.55,6.1
  Top Layer w0.3: U602.6@41.15,7.9 41.15,7.321 41.221,7.25 41.65,7.25 ; U602.7@41.65,7.9 41.65,7.25 ; 42.125,6.775 41.65,7.25
TH1: CN1.13 P1.1 | length 24.7
  Top Layer w0.6: P1.1@90.01,60.2 91.2,60.2 94.1,57.3 94.1,40.45 CN1.13@92.27,38.62
TH2: CN1.14 P2.1 | length 29.4
  Bottom Layer w0.6: P2.1@86.2,60.2 87.1,60.2 89,58.3 92.7,58.3 94.15,56.85 94.15,43.04 CN1.14@89.73,38.62
TLP5231_NC_A: U300.1
TLP5231_NC_B: U400.1
VCC2_A: C112.2 C113.2 C301.2 C302.1 C304.2 C305.1 C701.2 C703.2 D106.1 D107.2 D707.2 Q700.1 Q700.2 Q700.3 R115.2 TP6.1 U101.4 U300.13 | length 23.2
  Top Layer w0.3: TP6.1@47.6,53.8 49.1,52.3 C701.2@49.1,51.6 C305.1@49.1,49.8 48.95,49.65 C302.1@48.95,48.35 48.95,47.4 49.365,46.985 U300.13@49.365,45.75 ; C113.2@61.95,56.3 C112.2@63.25,56.3
  Bottom Layer w0.3: D707.2@37.9,53.9 38,54 C703.2@39.5,54 41.8,54 42.5,53.3 46.95,53.3 48.15,52.1 v1(50.05,52.1)
  other v1: 50.05,51.1 51.05,51.1 50.05,53.1 61.85,57.3 62.85,57.3 61.85,58.3 62.85,58.3
VCC2_B: C212.2 C213.2 C401.2 C402.1 C404.2 C405.1 C801.2 C803.2 D206.1 D207.2 D807.2 Q800.1 Q800.2 Q800.3 R215.2 TP13.1 U201.4 U400.13 | length 23.2
  Top Layer w0.3: C212.2@36.75,5.7 C213.2@38.05,5.7 ; U400.13@50.635,16.25 50.635,15.015 51.05,14.6 C402.1@51.05,13.65 51.05,12.35 C405.1@50.9,12.2 C801.2@50.9,10.4 50.9,9.7 TP13.1@52.4,8.2
  Bottom Layer w0.3: v1(49.95,9.9) 52.05,9.9 53.25,8.7 57.5,8.7 58.2,8 C803.2@60.5,8 62,8 D807.2@62.1,8.1
  other v1: 37.15,3.7 38.15,3.7 37.15,4.7 38.15,4.7 14.8,8 15.8,8 49.95,8.9 14.8,9 15.8,9 48.95,10.9 49.95,10.9
VDD: C1.2 C2.2 C16.2 C101.2 C102.2 C201.2 C202.2 CN1.2 D1.2 D100.2 D200.2 R100.2 R102.2 R200.2 R202.2 T100.3 T100.4 T200.3 T200.4 TP2.1 U1.1 U1.3 U3.1 U3.3 U100.3 U200.3 | length 29.2
  Top Layer w0.3: v1(35.5,31.05) 37.3,32.85 v1(37.3,35.8) ; v1(38.05,26.05) 38.25,26.25 U3.3@38.25,28.15 ; TP2.1@78.2,26.85 79.45,26.85 v1(79.8,27.2)
  Bottom Layer w0.3: R200.2@33,36.1 33.525,36.1 33.784,35.841 33.784,31.766 v1(34.5,31.05) ; v1(35.5,30.05) 37.1,30.05 37.75,29.4 37.75,27.5 38.05,27.2 v1(38.05,26.05) ; C2.2@35.675,32.05 36.55,32.05 U1.1@37.3,32.8 ; U1.3@37.3,34.7 v1(37.3,35.8) ; v1(60.5,31.05) 60.7,30.85 60.7,28.95 61.1,28.55 61.1,27.375 61.325,27.15 R100.2@61.9,27.15
  other v1: 80.8,27.2 86.35,27.2 87.35,27.2 34.5,30.05 60.5,32.05 61.5,32.05 62.5,32.05
VE_A: C106.1 C107.2 C108.1 C109.2 C110.1 C111.1 C112.1 C113.1 C300.2 C302.2 C303.2 C305.2 C500.2 C700.1 C701.1 C702.2 C703.1 C704.2 D104.2 D105.1 D701.1 D702.1 D806.2 P5.1 R109.2 R110.1 R111.2 R112.1 R114.1 R702.2 T100.6 T100.7 TP4.1 U300.16 U500.1 U500.3 | length 47.9
  Top Layer w0.5: D806.2@4.75,25.85 v1(4.75,27.117) ; TP4.1@38.9,51.5 40.35,51.5 v1@40.55,51.7 ; v1(45.25,51.2) C303.2@45.25,49.95 C300.2@45.25,48.6 45.25,46.63 45.555,46.325 U300.16@45.555,45.75
  GND2 w2: P5.1@32.86,60.2 35.51,57.55 41.45,57.55 45.85,53.15 45.85,51.8
  Bottom Layer w0.3: U500.3@59.2,50.35 60.25,49.3 63.2,49.3 64.1,50.2 64.1,51.5 v1(62.85,52.75) ; U500.1@59.2,52.25 59.5,52.55 C500.2@60.8,52.55
  Bottom Layer w0.5: v1(4.75,27.117) 11.6,33.967 v1(11.6,34.2) ; R114.1@80.15,52.3 v1(81.8,52.3)
  other v1: 13.25,44.55 14.25,44.55 13.25,45.55 14.25,45.55 71.75,49 71.75,50 70.75,51 71.75,51 46.25,51.2 40.55,51.75 41.55,51.75 45.25,52.2 46.25,52.2 82.8,52.3 40.55,52.75 41.55,52.75 61.85,52.75 81.8,53.3 82.8,53.3 61.85,53.75 62.85,53.75
VE_B: C206.1 C207.2 C208.1 C209.2 C210.1 C211.1 C212.1 C213.1 C400.2 C402.2 C403.2 C405.2 C600.2 C800.1 C801.1 C802.2 C803.1 C804.2 D204.2 D205.1 D801.1 D802.1 P12.1 R209.2 R210.1 R211.2 R212.1 R214.1 R802.2 T200.6 T200.7 TP14.1 U400.16 U600.1 U600.3 | length 38.1
  Top Layer w0.5: U400.16@54.445,16.25 54.445,15.675 54.75,15.37 C400.2@54.75,13.4 C403.2@54.75,12.05 v1(54.75,10.8) ; v1@59.45,10.3 59.65,10.5 TP14.1@61.1,10.5
  GND2 w2: 54.15,10.2 54.15,6.35 54.95,5.55 62.5,5.55 63.33,4.72 P12.1@63.33,1.8
  Bottom Layer w0.3: v1(37.15,9.25) 35.9,10.5 35.9,11.8 36.55,12.45 40,12.45 U600.3@40.8,11.65 ; C600.2@39.2,9.45 40.5,9.45 U600.1@40.8,9.75
  Bottom Layer w0.5: v1(17.5,13.75) 19.45,13.75 19.8,13.4 R214.1@21.25,13.4
  other v1: 18.2,4.1 19.2,4.1 18.2,5.1 19.2,5.1 37.15,8.25 38.15,8.25 38.15,9.25 58.45,9.25 59.45,9.25 53.75,9.8 54.75,9.8 58.45,10.25 59.45,10.25 53.75,10.8 28.25,11 29.25,11 28.25,12 28.25,13 13.156,17.897 14.156,17.897 13.156,18.897 14.156,18.897
VEE_A: C105.1 C107.1 C109.1 C300.1 C301.1 C303.1 C304.1 C500.1 C501.1 C502.1 C503.1 C504.1 C505.1 C506.1 C507.1 C508.1 C702.1 C704.1 D103.1 D105.2 D500.2 D708.1 Q501.2 Q701.4 Q702.4 R109.1 R111.1 R501.1 R504.1 R507.1 TP5.1 U300.9 U500.2 U501.2 U502.4 U503.2 | length 36.3
  Top Layer w0.2: U503.2@57.45,56.25 57.904,56.25
  Top Layer w0.3: Q701.4@41.15,49.15 41.7,49.15 42,49.45 C702.1@42,50.5 ; v1(49.75,57) 50.35,57 50.9,57.55 C507.1@53.9,57.55 C508.1@55.3,57.55 ; C301.1@52.75,48.4 53.15,48.8 C304.1@53.15,49.85 ; v1(52.925,54.35) 52.925,53.915 53.89,52.95 C505.1@55.3,52.95 C506.1@56.65,52.95 57.25,52.35 58.85,52.35 59.35,51.85 U502.4@59.35,51.4 ; v1(54.5,49.4) 55.1,50 TP5.1@55.1,51 ; 57.904,56.25 v1(58.5,56.25)
  Bottom Layer w0.3: D708.1@35.8,53.9 35.8,52.8 C704.1@36.45,52.15 ; v1(52.925,54.35) 52.45,54.825 R501.1@52.45,55.4 52.4,55.45 C502.1@52.4,56.7 53.98,56.7 54.48,57.2 U501.2@55.25,57.2 ; C503.1@58.2,53.9 C504.1@58.2,55.2 58.2,55.95 v1(58.5,56.25) ; U500.2@59.2,51.3 60.55,51.3 C500.1@60.8,51.05 ; v1(67.2,50.85) 67.25,50.9 D105.2@68.1,50.9 ; R111.1@69.3,49.5 69.3,48.5 R109.1@69.95,47.85
  Bottom Layer w0.5: v1(11.6,30.4) v1(11.6,31.55)
  other v1: 11.6,35.8 13.05,39.4 18.178,44.576 36.4,45.4 37.4,45.4 38.4,45.4 39.4,45.4 83.4,46.1 54.5,48.4 55.5,48.4 13.9,48.9 55.5,49.4 66.2,49.85 67.2,49.85 66.2,50.85 10.3,50.9 61.85,50.95 62.85,50.95 42.9,51.2 43.9,51.2 42.9,52.2 43.9,52.2 85.1,53.6 16.05,54.5 20.1,58.3
VEE_B: C205.1 C207.1 C209.1 C400.1 C401.1 C403.1 C404.1 C600.1 C601.1 C602.1 C603.1 C604.1 C605.1 C606.1 C607.1 C608.1 C802.1 C804.1 D203.1 D205.2 D600.2 D808.1 Q601.2 Q801.4 Q802.4 R209.1 R211.1 R601.1 R604.1 R607.1 TP16.1 U400.9 U600.2 U601.2 U602.4 U603.2 | length 35.2
  Top Layer w0.2: 42.096,5.75 U603.2@42.55,5.75
  Top Layer w0.3: v1(15.85,12.75) v1@15.856,12.756 ; U602.4@40.65,10.6 40.65,10.15 41.15,9.65 42.75,9.65 C606.1@43.35,9.05 C605.1@44.7,9.05 46.11,9.05 47.075,8.085 v1(47.075,7.65) ; v1(41.5,5.75) 42.096,5.75 ; C608.1@44.7,4.45 C607.1@46.1,4.45 49.45,4.45 50,5 v1(50.25,5) ; TP16.1@44.9,11 44.9,12 v1(45.5,12.6) ; C404.1@46.85,12.15 46.85,13.2 C401.1@47.25,13.6 ; C802.1@58,11.5 58,12.55 58.3,12.85 Q801.4@58.85,12.85
  Bottom Layer w0.3: R209.1@30.05,14.15 30.7,13.5 R211.1@30.7,12.5 ; D205.2@31.9,11.1 32.75,11.1 v1(32.8,11.15) ; C600.1@39.2,10.95 39.45,10.7 U600.2@40.8,10.7 ; v1(41.5,5.75) 41.8,6.05 C604.1@41.8,6.8 C603.1@41.8,8.1 ; U601.2@44.75,4.8 45.52,4.8 46.02,5.3 C602.1@47.6,5.3 47.6,6.55 R601.1@47.55,6.6 47.55,7.175 v1(47.075,7.65) ; C804.1@63.55,9.85 64.2,9.2 D808.1@64.2,8.1
  other v1: 16.4,3.7 12.1,3.8 79,3.8 84.4,3.8 89.8,3.8 94.4,3.8 79,8.8 84.4,8.8 89.8,8.8 95.2,8.8 56.1,9.8 57.1,9.8 11.55,10.05 56.1,10.8 57.1,10.8 37.15,11.05 38.15,11.05 33.8,11.15 32.8,12.15 33.8,12.15 95.2,12.3 44.5,12.6 44.5,13.6 45.5,13.6 79,13.8 84.4,13.8 60.6,16.6 61.6,16.6 62.6,16.6 63.6,16.6 79,16.6 83,16.6 16.25,19.05 10.4,25.2
VLED_A(NC): U300.10
VLED_B(NC): U400.10
pads on no net: ?.1 CN1.M1 CN1.M2

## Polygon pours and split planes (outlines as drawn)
NetC103_1 on Top Layer "3" (solid, remove dead copper, pour order 27): 78.1,31.4 78.7,32 78.7,36.4 78.1,37 72.7,37 72.7,35.3 73.8,34.2 73.8,33.3 73.95,33.15 74.554,33.15 74.9,32.804 74.9,31.65 75.15,31.4
NetD100_1 on Top Layer "NONET_L04_P-001" (solid, remove dead copper, pour order 296): 73.15,32.55 70.8,32.55 70.7,32.45 70.7,31.55 70.8,31.45 73.15,31.45 73.3,31.6 73.3,32.4
NetD102_2 on Top Layer "NONET_L04_P-001" (solid, remove dead copper, pour order 337): 79.7,47.7 79.9,47.5 79.9,45.2 79.7,45 75.3,45 75.2,45.1 75.2,46.7 76.2,47.7
NetD103_2 on Top Layer "NONET_L04_P-001" (solid, remove dead copper, pour order 343): 68.2,47.3 68.8,46.7 68.8,45.1 68.7,45 61.8,45 61.7,45.1 61.7,45.8 61.8,45.9 63.2,45.9 63.4,46.1 63.4,47.2 63.5,47.3
NetD200_1 on Top Layer "NONET_L04_P-001" (solid, remove dead copper, pour order 356): 26.85,29.4 29.2,29.4 29.35,29.55 29.35,30.35 29.2,30.5 26.85,30.5 26.7,30.35 26.7,29.55
NetC203_1 on Top Layer "3" (solid, remove dead copper, pour order 354): 21.9,30.6 21.3,30 21.3,25.6 21.9,25 27.3,25 27.3,26.65 26.2,27.75 26.2,28.7 26.05,28.85 25.446,28.85 25.1,29.196 25.1,30.35 24.85,30.6
GND on Top Layer "NONET_L04_P-001" (solid, remove dead copper, pour order 183): 26 vertices, not listed, extent 34.05,25 40.2,29.65
VE_A on Top Layer "NONET_L04_P-001" (solid, remove dead copper, pour order 365): 73.75,45 70.25,45 70.2,45.05 70.2,47.95 70.35,48.1 70.35,51.2 70.6,51.45 72.95,51.45 73.15,51.25 73.15,47.65 73.8,47 73.8,45.05
VEE_A on Top Layer "NONET_L04_P-001" (solid, remove dead copper, pour order 372): 65.5,51.65 65.9,51.25 68.9,51.25 69.5,50.65 69.5,48.35 69.35,48.2 68.7,48.2 68.6,48.3 64.5,48.3 63.25,49.55 61.7,49.55 61.25,50 61.25,51.3 61.6,51.65 63.25,51.65
NetD202_2 on Top Layer "NONET_L04_P-001" (solid, remove dead copper, pour order 394): 20.3,14.3 20.1,14.5 20.1,16.8 20.3,17 24.7,17 24.8,16.9 24.8,15.3 23.8,14.3
NetD202_2 on Top Layer "NONET_L04_P-001" (solid, remove dead copper, pour order 410): 20.3,14.3 20.1,14.5 20.1,16.8 20.3,17 24.7,17 24.8,16.9 24.8,15.3 23.8,14.3
NetD203_2 on Top Layer "NONET_L04_P-001" (solid, remove dead copper, pour order 413): 31.8,14.7 31.2,15.3 31.2,16.9 31.3,17 38.2,17 38.3,16.9 38.3,16.2 38.2,16.1 36.8,16.1 36.6,15.9 36.6,14.8 36.5,14.7
VE_B on Top Layer "NONET_L04_P-001" (solid, remove dead copper, pour order 415): 26.25,17 29.75,17 29.8,16.95 29.8,14.05 29.65,13.9 29.65,10.8 29.4,10.55 27.05,10.55 26.85,10.75 26.85,14.35 26.2,15 26.2,16.95
VEE_B on Top Layer "NONET_L04_P-001" (solid, remove dead copper, pour order 416): 34.5,10.35 34.1,10.75 31.1,10.75 30.5,11.35 30.5,13.65 30.65,13.8 31.3,13.8 31.4,13.7 35.5,13.7 36.75,12.45 38.3,12.45 38.6,12.15 38.6,10.55 38.4,10.35 36.75,10.35
NetD805_2 on Top Layer "NONET_L04_P-001" (solid, remove dead copper, pour order 437): 4.2,23.625 5.3,23.625 5.45,23.475 5.45,20.825 5.35,20.725 4.15,20.725 4.05,20.825 4.05,23.475 4.15,23.575
NetD804_2 on Top Layer "NONET_L04_P-001" (solid, remove dead copper, pour order 442): 4.2,19.025 5.3,19.025 5.45,18.875 5.45,16.225 5.35,16.125 4.15,16.125 4.05,16.225 4.05,18.875 4.15,18.975
NetD803_2 on Top Layer "NONET_L04_P-001" (solid, remove dead copper, pour order 443): 4.2,14.425 5.3,14.425 5.45,14.275 5.45,11.625 5.35,11.525 4.15,11.525 4.05,11.625 4.05,14.275 4.15,14.375
NetD705_2 on Top Layer "NONET_L04_P-001" (solid, remove dead copper, pour order 444): 4.15,50.525 5.25,50.525 5.4,50.375 5.4,47.725 5.3,47.625 4.1,47.625 4,47.725 4,50.375 4.1,50.475
NetD704_2 on Top Layer "NONET_L04_P-001" (solid, remove dead copper, pour order 445): 4.15,45.925 5.25,45.925 5.4,45.775 5.4,43.125 5.3,43.025 4.1,43.025 4,43.125 4,45.775 4.1,45.875
NetD703_2 on Top Layer "NONET_L04_P-001" (solid, remove dead copper, pour order 447): 4.15,41.325 5.25,41.325 5.4,41.175 5.4,38.525 5.3,38.425 4.1,38.425 4,38.525 4,41.175 4.1,41.275
GND on Top Layer "NONET_L04_P-001" (solid, remove dead copper, pour order 465): 61,37 60.7,36.7 60.7,35.3 60.9,35.1 64.7,35.1 65.4,35.8 65.4,36.7 65.1,37
5V_A on Top Layer "NONET_L04_P-001" (solid, remove dead copper, pour order 353): 41.1,34.8 40.9,34.6 40.9,32.55 41.6,31.85 44.35,31.85 44.55,32.05 44.55,32.2 42.9,33.85 41.85,33.85 41.6,34.1 41.6,34.7 41.5,34.8
GND on Top Layer "NONET_L04_P-001" (solid, remove dead copper, pour order 180): 43.3,28.6 43.5,28.4 43.5,25.9 43.2,25.6 41.6,25.6 41.35,25.85 41.35,26.95 41.85,27.45 41.85,28.55 41.9,28.6
GND on Top Layer "NONET_L04_P-001" (solid, remove dead copper, pour order 471): 45.7,28.7 44.3,28.7 44,28.4 44,26.4 43.8,26.2 43.8,25.4 44.2,25 45.8,25 45.9,25.1 45.9,28.5 45.8,28.6
GND on Top Layer "NONET_L04_P-001" (solid, remove dead copper, pour order 182): 54.1,36.8 54.1,34.55 54.35,34.3 57.2,34.3 57.45,34.3 57.9,34.3 57.9,36.15 57.15,36.9 54.15,36.9
NetD706_2 on Top Layer "NONET_L04_P-001" (solid, remove dead copper, pour order 385): 3.85,53.7 8.6,58.45 8.6,60.45 9.15,61 10.7,61 11.15,60.55 11.15,58.45 5.6,52.9 5.6,52.2 5.4,52 4.1,52 3.85,52.25
VCC2_B on Top Layer "NONET_L04_P-001" (solid, remove dead copper, pour order 418): 17,6.825 16.225,7.6 14.6,7.6 14.3,7.9 14.3,9.2 14.6,9.5 18,9.5 18.3,9.2 18.3,7.075 18.05,6.825
VEE_B on Top Layer "NONET_L04_P-001" (solid, remove dead copper, pour order 524): 13.2,23.15 13.2,25.9 9.6,25.9 9.6,22.775 9.6,21.85 10.1,21.35 13.15,21.35 15.6,18.9 15.6,13.8 14.8,13 14.8,12 15.1,11.7 16.6,11.7 17.1,12.2 17.1,19.25
GND on Top Layer "NONET_L04_P-001" (solid, remove dead copper, pour order 527): 43.5,25.2 43.3,25 36.75,25 36.5,25.25 36.5,27.35 37,27.85 37.15,27.85 38,27 41.4,27 41.85,27.45 43.2,27.45 43.5,27.15
VDD on Top Layer "2" (solid, remove dead copper, pour order 355): 25 vertices, not listed, extent 28.7,25 38.75,32.2
GND on Top Layer "NONET_L04_P-001" (solid, remove dead copper, pour order 492): 25 vertices, not listed, extent 34.25,33.15 44.1,37
VDD on Top Layer "2" (solid, remove dead copper, pour order 40): 21 vertices, not listed, extent 59.65,30.65 71.3,37
VCC2_A on Top Layer "NONET_L04_P-001" (solid, remove dead copper, pour order 322): 61.5,56.2 61.7,56 61.8,56 63.95,56 64.3,55.65 64.3,52.5 64.5,52.3 70.3,52.3 70.4,52.4 70.4,58.5 70.15,58.75 61.35,58.75 61.225,58.625 61.225,57.375 61.5,57.1
VE_A on Top Layer "NONET_L04_P-001" (solid, remove dead copper, pour order 552): 80.1,54 80.1,52.5 80.8,51.8 82.9,51.8 83.3,52.2 83.3,53.4 82.9,53.8 81.2,53.8 80.8,54.2 80.3,54.2
VE_B on Top Layer "NONET_L04_P-001" (solid, remove dead copper, pour order 555): 20.7,3.8 20.2,3.3 18,3.3 17.8,3.5 17.8,5.4 17.9,5.5 20.2,5.5 20.7,5
VE_A on Top Layer "NONET_L04_P-001" (solid, remove dead copper, pour order 607): 17 vertices, not listed, extent 38.3,50.2 41.95,53.1
VE_A on Top Layer "NONET_L04_P-001" (solid, remove dead copper, pour order 624): 14.45,46 14.85,45.6 14.85,40.9 14.35,40.4 12.25,40.4 12.15,40.5 12.15,41.45 12.6,41.9 12.6,43.1 12,43.7 11.85,43.7 11.8,43.75 11.8,45.9 11.9,46
VE_B on Top Layer "NONET_L04_P-001" (solid, remove dead copper, pour order 633): 14.356,19.347 14.756,18.947 14.756,14.247 14.256,13.747 12.156,13.747 12.056,13.847 12.056,14.797 12.506,15.247 12.506,16.447 11.906,17.047 11.756,17.047 11.706,17.097 11.706,19.247 11.806,19.347
VEE_B on Top Layer "r" (solid, remove dead copper, pour order 526): 17 vertices, not listed, extent 11.1,3.25 17.1,13.1
no net on Top Layer "NONET_L01_P643" (solid, pour order 643): 1,71 1,63 99,63 99,71
VEE_A on Top Layer "VEE_A_L01_P650" (solid, pour order 650): 85.4,54 85.7,53.7 85.7,47.4 84,45.7 83.2,45.7 82.9,46 82.9,50.8 83.9,51.8 83.9,53.9 84,54 84.1,54
NetC204_1 on Top Layer "re" (solid, remove dead copper, pour order 414): 23 vertices, not listed, extent 18.35,3.3 27.3,14.2
VEE_A on Top Layer "r" (solid, remove dead copper, pour order 601): 20 vertices, not listed, extent 52.4,45.15 55.9,51.3
NetR713_2 on Top Layer "NONET_L04_P-001" (solid, remove dead copper, pour order 655): 46.9,47.5 46.75,47.35 46.75,46.9 46.95,46.7 47.5,46.7 47.7,46.5 47.7,45.15 47.75,45.1 48.45,45.1 48.5,45.15 48.5,47.3 48.3,47.5 48.1,47.5
NetR700_2 on Top Layer "NONET_L04_P-001" (solid, remove dead copper, pour order 654): 50.2,47.55 49.94,47.29 49.94,46.89 50.25,46.58 50.25,45.15 50.3,45.1 51,45.1 51.05,45.15 51.05,46.5 51.25,46.7 51.35,46.7 51.65,47 51.65,47.28 51.38,47.55
NetD501_1 on Top Layer "NONET_L04_P-001" (solid, remove dead copper, pour order 653): 52.2,47.55 51.95,47.3 51.95,47.05 51.5,46.6 51.5,45.15 51.55,45.1 52.25,45.1 52.3,45.15 52.3,46.35 52.65,46.7 53.45,46.7 53.7,46.95 53.7,47.3 53.45,47.55
NetQ701_3 on Top Layer "NONET_L04_P-001" (solid, remove dead copper, pour order 657): 43.75,46.85 43.6,47 41,47 40.85,46.85 40.85,45.15 41,45 43.6,45 43.75,45.15
NetQ700_4 on Top Layer "NONET_L04_P-001" (solid, remove dead copper, pour order 661): 48.5,57.55 48.6,57.65 48.6,58.65 48.5,58.75 44.65,58.75 44.5,58.6 44.5,57.35 44.6,57.25 47.5,57.25 47.8,57.55
VE_A on Top Layer "NONET_L04_P-001" (solid, remove dead copper, pour order 373): 61.2,52.35 61.3,52.25 61.85,52.25 63.2,52.25 63.6,52.65 63.6,54.95 63.45,55.1 61.6,55.1 61.5,55 61.5,54.1 61.2,53.8
VCC2_A on Top Layer "re" (solid, remove dead copper, pour order 599): 25 vertices, not listed, extent 44.4,45.1 51.6,56.4
VEE_A on Top Layer "NONET_L04_P-001" (solid, remove dead copper, pour order 666): 19 vertices, not listed, extent 40.85,47.75 44.3,52.6
VEE_A on Top Layer "R" (solid, remove dead copper, pour order 670): 36.25,45 39.55,45 39.8,45.25 39.8,45.55 39.55,45.8 36.25,45.8 36,45.55 36,45.25
NetQ701_1 on Top Layer "NONET_L04_P-001" (solid, remove dead copper, pour order 677): 18 vertices, not listed, extent 25.85,46.3 40.5,49.45
NetQ700_5 on Top Layer "NONET_L04_P-001" (solid, remove dead copper, pour order 679): 26.3,57.75 25.9,57.35 25.9,54.7 26,54.6 38.6,54.6 38.75,54.45 38.75,53.8 39.1,53.45 39.95,53.45 41.15,54.65 41.15,57.4 40.8,57.75
VE_B on Top Layer "NONET_L04_P-001" (solid, remove dead copper, pour order 709): 38.55,9.75 38.15,9.75 36.8,9.75 36.4,9.35 36.4,7.05 36.55,6.9 38.4,6.9 38.5,7 38.5,7.9 38.8,8.2 38.8,9.5
VCC2_B on Top Layer "re" (solid, remove dead copper, pour order 710): 25 vertices, not listed, extent 48.4,5.6 55.6,16.9
VEE_B on Top Layer "r" (solid, remove dead copper, pour order 712): 20 vertices, not listed, extent 44.1,10.7 47.6,16.85
VE_B on Top Layer "NONET_L04_P-001" (solid, remove dead copper, pour order 713): 17 vertices, not listed, extent 58.05,8.9 61.7,11.8
NetD601_1 on Top Layer "NONET_L04_P-001" (solid, remove dead copper, pour order 714): 47.8,14.45 48.05,14.7 48.05,14.95 48.5,15.4 48.5,16.85 48.45,16.9 47.75,16.9 47.7,16.85 47.7,15.65 47.35,15.3 46.55,15.3 46.3,15.05 46.3,14.7 46.55,14.45
NetR800_2 on Top Layer "NONET_L04_P-001" (solid, remove dead copper, pour order 715): 49.8,14.45 50.06,14.71 50.06,15.11 49.75,15.42 49.75,16.85 49.7,16.9 49,16.9 48.95,16.85 48.95,15.5 48.75,15.3 48.65,15.3 48.35,15 48.35,14.72 48.62,14.45
NetR813_2 on Top Layer "NONET_L04_P-001" (solid, remove dead copper, pour order 716): 53.1,14.5 53.25,14.65 53.25,15.1 53.05,15.3 52.5,15.3 52.3,15.5 52.3,16.85 52.25,16.9 51.55,16.9 51.5,16.85 51.5,14.7 51.7,14.5 51.9,14.5
NetQ801_3 on Top Layer "NONET_L04_P-001" (solid, remove dead copper, pour order 717): 56.25,15.15 56.4,15 59,15 59.15,15.15 59.15,16.85 59,17 56.4,17 56.25,16.85
NetQ800_4 on Top Layer "NONET_L04_P-001" (solid, remove dead copper, pour order 718): 51.5,4.45 51.4,4.35 51.4,3.35 51.5,3.25 55.35,3.25 55.5,3.4 55.5,4.65 55.4,4.75 52.5,4.75 52.2,4.45
VEE_B on Top Layer "NONET_L04_P-001" (solid, remove dead copper, pour order 720): 19 vertices, not listed, extent 55.7,9.4 59.15,14.25
no net on Top Layer "R" (solid, remove dead copper, pour order 721): 63.75,17 60.45,17 60.2,16.75 60.2,16.45 60.45,16.2 63.75,16.2 64,16.45 64,16.75
NetQ801_1 on Top Layer "NONET_L04_P-001" (solid, remove dead copper, pour order 722): 18 vertices, not listed, extent 59.5,12.55 74.15,15.7
NetQ800_5 on Top Layer "NONET_L04_P-001" (solid, remove dead copper, pour order 724): 73.7,4.25 74.1,4.65 74.1,7.3 74,7.4 61.4,7.4 61.25,7.55 61.25,8.2 60.9,8.55 60.05,8.55 58.85,7.35 58.85,4.6 59.2,4.25
VEE_A on Top Layer "NONET_L04_P-001" (solid, remove dead copper, pour order 745): 19.5,58.75 16.2,55.45 13.8,55.45 9.6,51.25 9.6,48.65 10.25,48 10.3,48.05 14.15,48.05 18.063,44.137 22.887,44.137 24.45,45.7 24.45,58.2 23.9,58.75
NetD501_1 on Top Layer "NONET_L04_P-001" (solid, remove dead copper, pour order 750): 57.5,46.75 55.95,46.75 55.55,46.35 55.55,45.3 55.85,45 58.95,45 59.35,45.4 59.35,47.35 59.158,47.542 58.292,47.542
NetD601_1 on Top Layer "NONET_L04_P-001" (solid, remove dead copper, pour order 751): 42.5,15.25 44.05,15.25 44.45,15.65 44.45,16.7 44.15,17 41.05,17 40.65,16.6 40.65,14.65 40.842,14.458 41.708,14.458
VCC2_B on Top Layer "NONET_L04_P-001" (solid, remove dead copper, pour order 553): 38.5,6 36.05,6 35.7,6.35 35.7,9.5 35.5,9.7 29.7,9.7 29.6,9.6 29.6,3.5 29.85,3.25 38.5,3.25 38.75,3.5 38.75,4.7 38.5,4.95
VE_B on Top Layer "NONET_L04_P-001" (solid, remove dead copper, pour order 711): 24 vertices, not listed, extent 52.2,9.4 55.45,17
VE_A on Top Layer "NONET_L04_P-001" (solid, remove dead copper, pour order 754): 24 vertices, not listed, extent 44.55,45 47.8,52.6
no net on Top Layer "NONET_L01_P752" (solid, pour order 752): 1,-1 1,-9 99,-9 99,-1
5V_B on Top Layer "NONET_L04_P-001" (solid, remove dead copper, pour order 174): 17 vertices, not listed, extent 40.15,27.2 48.8,31.35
